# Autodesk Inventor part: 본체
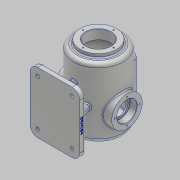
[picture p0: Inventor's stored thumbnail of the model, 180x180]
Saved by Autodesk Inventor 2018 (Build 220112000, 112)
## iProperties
Created: 2021-11
Part Number: 본체
Material: 알루미늄 6061
Document SubType Name: Modeling
Designer: home
Density: 2.7 g/cm^3
Appearance: 알루미늄 - 평지
Mass: 3540.47 g
Surface Area: 2404.16 cm^2
Volume: 1311.28 cm^3
Author: home
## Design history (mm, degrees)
sketch "스케치1"
  geometry: L1 (0, 0)-(65, 0); L2 (65, 0)-(65, -175.993); L3 (0, -200)-(0, 0); L4 (0, -100)-(0, -200); A1 r 100 centre (0, -100) between (0, -200) and (65, -175.993)
  constraints: 8 end point, 2 parallel, 2 point on circle, 1 centre point, 1 coincident, 1 horizontal, 1 midpoint, 1 perpendicular, 1 tangent
  dimensions: "d3" = 100 radius of A1; "d4" = 65 distance between parallel lines of L2 L3
revolve "회전1" sketch "스케치1" stored, may be unused: angle "d5" = 90 deg
sketch "스케치2"
  geometry: C1 r 47.5 at (0, 0); 1 further point
  constraints: 1 centre point, 1 coincident
  dimensions: "d6" = 95 diameter of C1
extrude "돌출1" join sketch "스케치2" distance "d7" = 10; taper "d8" = 0 deg
node "작업 평면1"
sketch "스케치3"
  geometry: L1 (30, -40)-(-30, -40); L2 (-30, -40)-(-30, -160); L3 (-30, -160)-(30, -160); L4 (30, -160)-(30, -40); L5 (47.5, 10)-(-47.5, 10) reference; 2 further points
  constraints: 8 end point, 2 parallel, 1 horizontal, 1 midpoint, 1 perpendicular, 1 vertical alignment
  dimensions: "d10" = 60 distance of L3.end L2.end; "d11" = 120 distance of L2.end L1.end; "d12" = 50 distance between parallel lines of L5 L1
extrude "돌출2" join sketch "스케치3" stored distance "d13" = 10; taper "d14" = 0 deg
sketch "스케치4"
  geometry: L1 (-30, 160)-(-30, 40) reference; L2 (-30, 100)-(30, 100); L3 (30, 160)-(30, 40) reference; L4 (0, 40)-(0, 160); L5 (-24, 45)-(0, 45); L6 (-25, 100)-(-25, 130); L7 (-30, 40)-(30, 40) reference; L8 (25, 100)-(25, 126); L9 (0, 155)-(-18, 155); L10 (30, 160)-(-30, 160) reference; 1 further point
  constraints: 12 end point, 4 point on line, 3 vertical, 2 midpoint, 1 horizontal, 1 perpendicular
  dimensions: "d15" = 5 distance between parallel lines of L1 L6; "d16" = 5 distance between parallel lines of L7 L5; "d24" = 5 distance between parallel lines of L10 L9; "d25" = 5 distance between parallel lines of L3 L8; "d156" = 30 distance between parallel lines of L3 L4; "d157" = 34 distance from line of L8.end L10; "d158" = 0 distance from line of L4.end L10; "d159" = 120 distance from line of L4.start L10; "d160" = 48 distance from line of L9.end L3; "d161" = 54 distance from line of L5.start L3; "d162" = 30 distance from line of L6.end L10
hole "구멍1" sketch "스케치4" at (-25, 100), (0, 45), (25, 100), (0, 155) diameter "d17" = 3.242; stored, may be unused: countersink angle "d21" = 90 deg, drill point angle "d23" = 118 deg; dims "d18" = 9, "d19" = 4, "d20" = 2, "d22" = 11
node "작업 평면2"
sketch "스케치5"
  geometry: L1 (70, -160)-(70, -40) reference; L2 (70, -98.379)-(70, -101.621) reference; L3 (70, -100)-(100, -100); C1 r 40 at (0, -117); 1 further point
  constraints: 2 end point, 1 centre point, 1 horizontal, 1 midpoint, 1 vertical alignment
  dimensions: "d28" = 80 diameter of C1; "d29" = 17 distance from line of C1.centre L3; "d163" = 30 distance from line of L3.end L2
extrude "돌출3" join sketch "스케치5" stored distance "d30" = 10; taper "d31" = 0 deg
sketch "스케치6" dims "d32" = 65
  geometry: L1 (0, 0)-(0, 32.5); 1 further point
  constraints: 2 end point, 1 vertical, 1 vertical alignment, 2 other
  dimensions: "d33" = 117 distance from line of point (117, 0) L1; "d34" = 121.43002 distance of point (117, 0) L1.end
hole "구멍2" sketch "스케치6" at (0, 32.5) diameter "d35" = 3.242; stored, may be unused: countersink angle "d39" = 90 deg, drill point angle "d41" = 118 deg; dims "d36" = 11, "d37" = 4, "d38" = 2, "d40" = 13
hole "구멍3" diameter "d47" = 42; stored, may be unused: countersink angle "d51" = 90 deg, drill point angle "d53" = 0 deg; dims "d45" = 10, "d46" = 10, "d48" = 42, "d49" = 52, "d50" = 18, "d52" = 60
sketch "스케치7"
  geometry: L1 (0, 10)-(0, -190); L2 (0, 10)-(32.5, 10); L3 (32.5, 10)-(32.5, -15); L4 (65, 0)-(65, -175.993) reference; L5 (58.532, -15)-(150.532, -15); L6 (32.5, -15)-(55, -15); L7 (55, -15)-(55, -171.239); A1 r 100 centre (0, -100) between (-65, -175.993) and (65, -175.993) reference; A2 r 90 centre (0, -100) between (0, -190) and (55, -171.239); 1 further point
  constraints: 12 end point, 2 parallel, 2 perpendicular, 2 point on circle, 1 centre point, 1 horizontal, 1 vertical
  dimensions: "d54" = 10 radial gap between concentric circles of A1 A2; "d61" = 200 distance of L1.start L1.end; "d63" = 10 distance between parallel lines of L7 L4; "d64" = 32.5 distance between parallel lines of L3 L4; "d65" = 130 diameter of L4 L1; "d66" = 0 distance between parallel lines of L6 L5; "d67" = 25 distance between parallel lines of L2 L5; "d68" = 85.53249 distance from line of L5.end L4; "d69" = 6.46751 distance from line of L5.start L4
revolve "회전2" sketch "스케치7" stored, may be unused: angle "d70" = 90 deg
sketch "스케치8" dims "d71" = 80
  geometry: L1 (0, 0)-(0, 40); 1 further point
  constraints: 2 end point, 1 coincident, 1 vertical, 1 vertical alignment, 2 other
hole "구멍4" sketch "스케치8" at (0, 40) diameter "d72" = 3.242; stored, may be unused: countersink angle "d76" = 90 deg, drill point angle "d78" = 118 deg; dims "d73" = 11, "d74" = 52, "d75" = 18, "d77" = 13
sketch "스케치9"
  geometry: L1 (-20, 50)-(20, 50); L2 (20, 50)-(20, 150); L3 (20, 150)-(-20, 150); L4 (-20, 150)-(-20, 50); L5 (-30, 160)-(-30, 40) reference; L6 (30, 40)-(30, 160) reference; L7 (30, 160)-(-30, 160) reference; L8 (-30, 40)-(30, 40) reference; 1 further point
  constraints: 8 end point, 2 parallel, 1 horizontal, 1 perpendicular
  dimensions: "d82" = 10 distance between parallel lines of L5 L4; "d83" = 10 distance between parallel lines of L6 L2; "d84" = 10 distance between parallel lines of L7 L3; "d85" = 10 distance between parallel lines of L8 L1
extrude "돌출4" cut sketch "스케치9" distance "d86" = 30; taper "d87" = 0 deg
node "작업 평면3"
sketch "스케치10"
  geometry: L1 (65, -20)-(-65, -20); L2 (-65, -180)-(65, -180); L3 (65, -180)-(65, -20); L4 (-30, -160)-(30, -160) reference; L5 (47.5, 10)-(-47.5, 10) reference; 3 further points; 1 other entity
  constraints: 6 end point, 2 horizontal, 2 midpoint, 1 parallel, 1 vertical, 1 vertical alignment, 3 other
  dimensions: "d89" = 130 distance of L2.end L2.start; "d90" = 160 distance of L2.start L1.end; "d91" = 30 distance between parallel lines of L5 L1
extrude "돌출5" join sketch "스케치10" distance "d92" = 14; taper "d93" = 0 deg
node "작업 평면4"
sketch "스케치11"
  geometry: L1 (0, 14)-(130, 14) reference; L2 (15, 14)-(115, 14); L3 (15, 14)-(31.191, 58.485); L4 (115, 14)-(98.809, 58.485); L5 (115, 14)-(152.246, 14); A1 r 65 centre (65, 114) between (31.191, 58.485) and (98.809, 58.485) reference; 2 further points
  constraints: 8 end point, 2 point on circle, 2 point on line, 1 horizontal, 1 midpoint, 1 vertical alignment
  dimensions: "d95" = 100 distance of L2.start L2.end; "d96" = 110 deg angle of L1 L3; "d97" = 110 deg angle of L5 L4; "d164" = 35 distance from line of L5.end L4
extrude "돌출6" join sketch "스케치11" stored distance "d98" = 14; taper "d99" = 0 deg
sketch "스케치12"
  geometry: L1 (-100, -40)-(-65, -52.739); L2 (-65, 0)-(-65, -175.993) reference; 1 further point
  constraints: 2 end point, 1 point on line
  dimensions: "d165" = 110 deg angle of L1 L2; "d166" = 71.78972 distance from line of point (0, 0) L1; "d167" = 35 distance from line of L1.start L2
feature "리브1" sketch "스케치12" dims "d102" = 1, "d103" = 14, "d104" = 0, "d105" = 0, "d106" = 1, "d107" = 1
fillet "모깎기1" dims "d108" = 20, "d145" = 10, "d146" = 5, "d147" = 15
hole "구멍5" diameter "d111" = 9; stored, may be unused: countersink angle "d115" = 90 deg, drill point angle "d117" = 0 deg; dims "d109" = 10, "d110" = 10, "d112" = 11, "d113" = 18, "d114" = 2, "d116" = 42
hole "구멍6" diameter "d120" = 9; stored, may be unused: countersink angle "d124" = 90 deg, drill point angle "d126" = 0 deg; dims "d118" = 10, "d119" = 10, "d121" = 11, "d122" = 18, "d123" = 2, "d125" = 42
hole "구멍7" diameter "d129" = 9; stored, may be unused: countersink angle "d133" = 90 deg, drill point angle "d135" = 0 deg; dims "d127" = 10, "d128" = 10, "d130" = 11, "d131" = 18, "d132" = 2, "d134" = 42
hole "구멍8" diameter "d138" = 9; stored, may be unused: countersink angle "d142" = 90 deg, drill point angle "d144" = 0 deg; dims "d136" = 10, "d137" = 10, "d139" = 11, "d140" = 18, "d141" = 2, "d143" = 42
chamfer "모따기1" distance "d148" = 1; stored, may be unused: second distance "d149" = 2, angle "d150" = 45 deg
fillet "모깎기2" dims "d151" = 3, "d155" = 0.3
sketch "스케치13"
  geometry: L1 (0, 0)-(120, 0) reference; L2 (120, 14)-(0, 14) reference; 3 further points
  constraints: 1 midpoint, 1 vertical alignment, 1 other
  dimensions: "d152" = 5 distance from line of L1 point (60, 5)
feature "엠보싱1" sketch "스케치13" dims "d3" = 100, "d4" = 65, "d12" = 50, "d153" = 0.5, "d154" = 0
node "솔리드1"
pattern_circular "원형 패턴1" dims angle "d43" = 360 deg
pattern_circular "원형 패턴2" dims angle "d80" = 360 deg
mirror "미러1"
mirror "미러2"
other parameters: "d26" = -75, "d88" = -114
